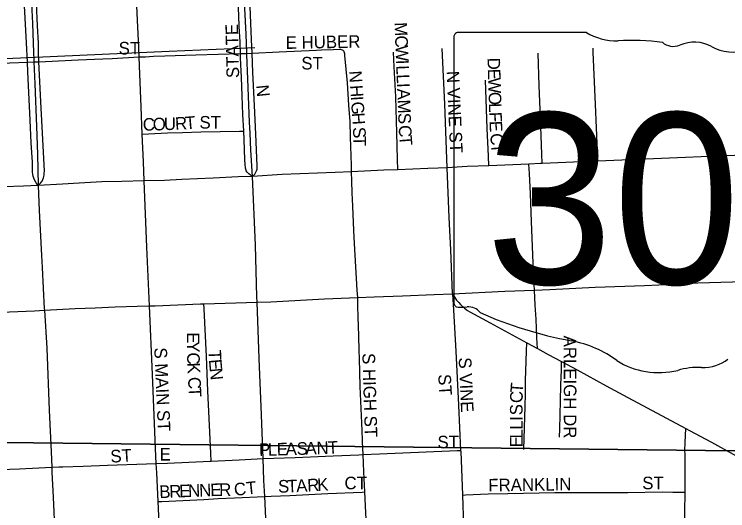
# Model space of a CAD drawing. Extents: x -97 to 34, y -21 to 22.
# Drawn here: x 5.626 to 6.163, y 19.422 to 19.796 of the extents above; entities that cross this region are included whole.
import ezdxf

# ---------------------------------------------------------------- set-up
doc = ezdxf.new("R2010")
doc.units = 0
for name, color, linetype in [('GM_X_City_Street', 7, 'Continuous'), ('GM_X_City_Street_Text', 7, 'Continuous'), ('GM_X_Rail_Line', 7, 'Continuous'), ('GM_X_Section', 7, 'Continuous'), ('GM_X_State_Location', 7, 'Continuous'), ('GM_X_State_Route', 7, 'Continuous'), ('GM_X_State_Shield', 7, 'Continuous')]:
    doc.layers.add(name, color=color, linetype=linetype)

msp = doc.modelspace()

# ---------------------------------------------------------------- linework, layer by layer
at = {"layer": 'GM_X_City_Street'}
for points in [[(5.71984, 19.76387), (5.71944, 19.77089), (5.71848, 19.79156), (5.71627, 19.84134), (5.71468, 19.87863), (5.7134, 19.90538)], [(5.64434, 19.76026), (5.64409, 19.76775), (5.64386, 19.77424), (5.64327, 19.7874), (5.64248, 19.8043), (5.64189, 19.82119), (5.64071, 19.84279), (5.63971, 19.87305), (5.63831, 19.90448)], [(5.63571, 19.75992), (5.63503, 19.77443), (5.63345, 19.80233), (5.63226, 19.82629), (5.63127, 19.85006), (5.63029, 19.87677), (5.63016, 19.87977)], [(5.79599, 19.76644), (5.7957, 19.77526), (5.79511, 19.78685), (5.79491, 19.7951), (5.79333, 19.82692), (5.79319, 19.82924)], [(5.80474, 19.76668), (5.80433, 19.77702), (5.80296, 19.8082), (5.80228, 19.82381), (5.80206, 19.82962)], [(5.71984, 19.76387), (5.72445, 19.76407), (5.73055, 19.76433), (5.73918, 19.7647), (5.76245, 19.7655), (5.79599, 19.76644)], [(5.79599, 19.76644), (5.80006, 19.76655), (5.80077, 19.76657), (5.80474, 19.76668)], [(5.79845, 19.70802), (5.79788, 19.72046), (5.79729, 19.7346), (5.79689, 19.74835), (5.7961, 19.76289), (5.79599, 19.76644)], [(5.80474, 19.76668), (5.8251, 19.76778), (5.8533, 19.76903), (5.85707, 19.76923), (5.86585, 19.76954), (5.87049, 19.76971), (5.87123, 19.76962), (5.87195, 19.76949), (5.87257, 19.76925), (5.87301, 19.76903), (5.87363, 19.76853)], [(5.80513, 19.67386), (5.80685, 19.67552), (5.80771, 19.67697), (5.80818, 19.67797), (5.80856, 19.67946), (5.80861, 19.68035), (5.80866, 19.68173), (5.80749, 19.70559), (5.80663, 19.72735), (5.8054, 19.75224), (5.80474, 19.76668)], [(5.87971, 19.67732), (5.87956, 19.68234), (5.87893, 19.70348), (5.8785, 19.71536), (5.87765, 19.72753), (5.87648, 19.74446), (5.87466, 19.76485), (5.87457, 19.76616), (5.87441, 19.76685), (5.87416, 19.76759), (5.87397, 19.76809), (5.87363, 19.76853)], [(5.91454, 19.67892), (5.91433, 19.68698), (5.91383, 19.70674), (5.91296, 19.73388), (5.91177, 19.7564), (5.91118, 19.76754)], [(5.95158, 19.6803), (5.94981, 19.72821), (5.94777, 19.7701)], [(6.02321, 19.68359), (6.02294, 19.69067), (6.0219, 19.71818), (6.021, 19.7422), (6.02007, 19.76675)], [(6.06508, 19.68531), (6.06477, 19.69278), (6.06326, 19.72813), (6.0616, 19.76752), (6.06143, 19.77055)], [(5.56126, 19.75673), (5.56745, 19.75698), (5.60894, 19.75891), (5.63571, 19.75992)], [(5.63571, 19.75992), (5.64055, 19.76011), (5.64155, 19.76015), (5.64434, 19.76026)], [(5.64379, 19.66695), (5.64221, 19.6691), (5.64078, 19.67186), (5.64004, 19.67399), (5.63974, 19.67542), (5.63954, 19.67726), (5.63937, 19.68467), (5.63838, 19.6992), (5.63759, 19.71629), (5.63602, 19.75263), (5.63571, 19.75992)], [(5.64379, 19.66695), (5.64536, 19.66876), (5.64668, 19.67038), (5.64765, 19.67293), (5.64812, 19.67475), (5.64829, 19.6763), (5.64846, 19.67775), (5.64675, 19.71132), (5.64564, 19.72999), (5.64466, 19.75027), (5.64434, 19.76026)], [(5.64434, 19.76026), (5.64913, 19.76043), (5.67383, 19.76162), (5.69238, 19.76252), (5.69953, 19.76275), (5.71984, 19.76387)], [(5.72212, 19.70578), (5.72135, 19.72628), (5.72007, 19.75727), (5.71984, 19.76387)], [(5.98298, 19.68197), (5.98265, 19.68914), (5.9817, 19.71003), (5.98051, 19.74646)], [(5.72212, 19.70578), (5.74113, 19.70662), (5.75248, 19.707), (5.7662, 19.70747), (5.79521, 19.70797), (5.79845, 19.70802)], [(5.80513, 19.67386), (5.80355, 19.67478), (5.80238, 19.67575), (5.80116, 19.67697), (5.80036, 19.67815), (5.80027, 19.67851), (5.79984, 19.68014), (5.79958, 19.68311), (5.7994, 19.68624), (5.79873, 19.70176), (5.79845, 19.70802)], [(5.72347, 19.67047), (5.7231, 19.68486), (5.72212, 19.70578)], [(6.01729, 19.5883), (6.01713, 19.59209), (6.017, 19.59522), (6.01644, 19.60855), (6.01511, 19.64001), (6.01424, 19.66069), (6.0135, 19.67603), (6.01316, 19.68319)], [(5.8843, 19.5826), (5.8839, 19.58809), (5.88193, 19.62328), (5.88139, 19.63315), (5.88056, 19.65153), (5.88011, 19.66147), (5.87988, 19.67028), (5.87971, 19.67732)], [(5.72755, 19.5763), (5.7256, 19.6205), (5.72347, 19.67047)], [(6.01958, 19.54419), (6.01921, 19.55233), (6.01856, 19.56626), (6.01795, 19.57692), (6.01729, 19.5883)], [(5.95576, 19.58544), (5.9565, 19.57314), (5.95805, 19.54225), (5.96017, 19.50147), (5.96177, 19.46753)], [(5.77401, 19.45943), (5.77365, 19.46553), (5.7732, 19.47589), (5.77157, 19.51235), (5.77042, 19.53827), (5.76866, 19.57404), (5.76846, 19.57799)], [(5.88827, 19.46441), (5.88788, 19.47391), (5.88779, 19.47532), (5.8877, 19.48214), (5.88732, 19.48798), (5.88613, 19.51563), (5.88551, 19.53685), (5.88536, 19.54242), (5.88506, 19.55382), (5.88468, 19.56807), (5.88447, 19.57621), (5.8843, 19.5826)], [(5.73268, 19.45753), (5.73243, 19.46283), (5.72982, 19.52467), (5.72755, 19.5763)], [(6.00938, 19.46825), (6.00983, 19.48455), (6.01027, 19.50071), (6.01047, 19.50976), (6.0107, 19.52014), (6.01113, 19.53477), (6.01144, 19.54245), (6.01168, 19.54848)], [(6.03623, 19.47755), (6.03644, 19.48387), (6.037, 19.50478), (6.03731, 19.51652), (6.03763, 19.52829), (6.03779, 19.5344)], [(6.13076, 19.43609), (6.13082, 19.44287), (6.13071, 19.46451), (6.13066, 19.4674), (6.13086, 19.47346), (6.13122, 19.48405)], [(5.88827, 19.46441), (5.9008, 19.46495), (5.95337, 19.46723), (5.95927, 19.46745), (5.96177, 19.46753)], [(5.96177, 19.46753), (5.96181, 19.46666), (5.96306, 19.43384)], [(5.73268, 19.45753), (5.74119, 19.45792), (5.77318, 19.45939), (5.77401, 19.45943)], [(5.77401, 19.45943), (5.79504, 19.46039), (5.81305, 19.46133)], [(5.81305, 19.46133), (5.83708, 19.46224), (5.86569, 19.46339), (5.8851, 19.46424), (5.88827, 19.46441)], [(5.88954, 19.4362), (5.88882, 19.45136), (5.88827, 19.46441)], [(5.5894, 19.45308), (5.59252, 19.45286), (5.59702, 19.45276), (5.60216, 19.45276), (5.60759, 19.45287), (5.62955, 19.45365), (5.65397, 19.45497)], [(5.65397, 19.45497), (5.65933, 19.45505), (5.66239, 19.45509), (5.67764, 19.45571), (5.69594, 19.45635), (5.72521, 19.45749), (5.73268, 19.45753)], [(5.73394, 19.42898), (5.73299, 19.45068), (5.73268, 19.45753)], [(5.73394, 19.42898), (5.73673, 19.42911), (5.76855, 19.43056), (5.77932, 19.43126), (5.79159, 19.43167), (5.81426, 19.43276)], [(5.81426, 19.43276), (5.81913, 19.43304), (5.83324, 19.43358), (5.86175, 19.43493), (5.88776, 19.43612), (5.88954, 19.4362)], [(5.89109, 19.40348), (5.89103, 19.40499), (5.88954, 19.4362)], [(5.96306, 19.43384), (5.9655, 19.43395), (5.98248, 19.43476), (5.99727, 19.43516), (6.03263, 19.43577), (6.05351, 19.43567), (6.07109, 19.43577), (6.08753, 19.43589), (6.11356, 19.43618), (6.12149, 19.4361), (6.12864, 19.43609), (6.13076, 19.43609)], [(5.96306, 19.43384), (5.96394, 19.41059), (5.96445, 19.39593), (5.96525, 19.37289)], [(6.1299, 19.37581), (6.13076, 19.43609)], [(5.7355, 19.39632), (5.73394, 19.42898)]]:
    msp.add_lwpolyline(points, dxfattribs=at)
at = {"layer": 'GM_X_Rail_Line'}
for points in [[(5.12506, 19.74133), (5.25397, 19.74658), (5.45064, 19.75541), (5.56834, 19.76047), (5.74228, 19.76816), (5.80143, 19.7707)], [(5.80143, 19.7707), (5.80685, 19.77094)]]:
    msp.add_lwpolyline(points, dxfattribs=at)
at = {"layer": 'GM_X_Section'}
for points in [[(5.59805, 20.47457), (6.61045, 20.46615), (6.60805, 19.46219), (5.59615, 19.47364)], [(5.59615, 19.47364), (6.60805, 19.46219), (6.59547, 18.46625), (5.59082, 18.47236)]]:
    msp.add_lwpolyline(points, close=True, dxfattribs=at)
at = {"layer": 'GM_X_State_Route'}
for points in [[(5.80294, 19.71473), (5.8016, 19.74704), (5.8008, 19.76569), (5.80077, 19.76657), (5.80019, 19.78098), (5.79942, 19.80041), (5.79882, 19.81541), (5.79809, 19.82947), (5.79783, 19.83465), (5.79637, 19.86532), (5.79443, 19.90607)], [(5.63488, 19.88036), (5.63635, 19.85068), (5.63754, 19.82581), (5.63863, 19.80411), (5.63934, 19.78901), (5.64023, 19.76731), (5.64048, 19.76193), (5.64055, 19.76011), (5.64121, 19.74363), (5.64237, 19.71146), (5.64311, 19.69074), (5.64379, 19.66695)], [(5.80513, 19.67386), (5.8039, 19.69366), (5.80328, 19.70639), (5.80294, 19.71473)], [(6.2824, 19.69496), (6.27871, 19.69569), (6.27535, 19.69613), (6.2727, 19.69636), (6.26992, 19.69643), (6.26402, 19.69609), (6.26088, 19.69554), (6.25635, 19.69475), (6.25295, 19.69377), (6.25069, 19.69347), (6.24738, 19.69338), (6.24339, 19.69315), (6.21975, 19.6918), (6.19129, 19.69058), (6.17504, 19.68989), (6.16102, 19.68929), (6.06508, 19.68531), (6.0528, 19.6848), (6.02321, 19.68359), (6.022, 19.68354), (6.01316, 19.68319)], [(5.95158, 19.6803), (5.94476, 19.68005), (5.93708, 19.67979), (5.91454, 19.67892), (5.90386, 19.67851), (5.87971, 19.67732), (5.86728, 19.6767), (5.82752, 19.6752), (5.80513, 19.67386)], [(6.01316, 19.68319), (5.98298, 19.68197), (5.96675, 19.68133), (5.95158, 19.6803)], [(5.95576, 19.58544), (5.9545, 19.61853), (5.95325, 19.64283), (5.95158, 19.6803)], [(5.80513, 19.67386), (5.7942, 19.67345), (5.77557, 19.67252), (5.75177, 19.67144), (5.73886, 19.67086), (5.72347, 19.67047), (5.70681, 19.67006), (5.69163, 19.66967), (5.67471, 19.66884), (5.66198, 19.66793), (5.64379, 19.66695)], [(5.80859, 19.57918), (5.80843, 19.58323), (5.80722, 19.62219), (5.80513, 19.67386)], [(5.64379, 19.66695), (5.63272, 19.66657), (5.61797, 19.66597)], [(5.64379, 19.66695), (5.64439, 19.64813), (5.64623, 19.61441), (5.64678, 19.60515), (5.64836, 19.5741), (5.64841, 19.57304)], [(5.95576, 19.58544), (5.99491, 19.58745), (6.01729, 19.5883), (6.02898, 19.58874), (6.06304, 19.59041), (6.10023, 19.59161), (6.12188, 19.59268), (6.14044, 19.59362), (6.18384, 19.59508), (6.19092, 19.59539), (6.23649, 19.5976), (6.25248, 19.59818), (6.26864, 19.59883)], [(5.80859, 19.57918), (5.81893, 19.57949), (5.8594, 19.58157), (5.8843, 19.5826), (5.89674, 19.58312), (5.9181, 19.58393), (5.94179, 19.58493), (5.95576, 19.58544)], [(5.95576, 19.58544), (5.95876, 19.58069), (5.9603, 19.57889), (5.96164, 19.57748), (5.96459, 19.57473), (5.96698, 19.57292), (5.9687, 19.57194), (5.9839, 19.56359), (6.01168, 19.54848), (6.01958, 19.54419), (6.02762, 19.53981), (6.03779, 19.5344), (6.0496, 19.52813), (6.07143, 19.51623), (6.08773, 19.50736), (6.13122, 19.48405), (6.13415, 19.48248), (6.15056, 19.47363), (6.18319, 19.45558)], [(5.64841, 19.57304), (5.67162, 19.5744), (5.68676, 19.57493), (5.70181, 19.57555), (5.71825, 19.57602), (5.72755, 19.5763), (5.73176, 19.57648), (5.766, 19.57792), (5.76846, 19.57799), (5.80859, 19.57918)], [(5.81579, 19.40021), (5.81426, 19.43276), (5.81368, 19.44493), (5.81305, 19.46133), (5.81178, 19.49422), (5.81007, 19.53664), (5.80859, 19.57918)], [(5.33723, 19.56139), (5.33859, 19.56129), (5.35022, 19.56126), (5.35928, 19.5612), (5.36561, 19.5614), (5.37168, 19.5616), (5.39822, 19.56258), (5.39939, 19.56263), (5.43943, 19.56406), (5.46119, 19.56492), (5.47611, 19.56559), (5.49206, 19.56631), (5.55649, 19.56914), (5.56633, 19.56957), (5.58408, 19.57029), (5.64107, 19.5726), (5.64841, 19.57304)], [(5.64841, 19.57304), (5.65021, 19.54453), (5.65196, 19.49769), (5.65352, 19.46651), (5.65397, 19.45497), (5.65413, 19.45102), (5.65492, 19.4323), (5.65622, 19.40416), (5.65663, 19.39506)]]:
    msp.add_lwpolyline(points, dxfattribs=at)
at = {"layer": 'GM_X_State_Shield'}
for p, q in [((6.05653, 19.78232), (5.96001, 19.78232)), ((5.95676, 19.77887), (5.95676, 19.57875))]:
    msp.add_line(p, q, dxfattribs=at)
for centre, major_axis, start_param, end_param in [((5.96054, 19.7793), (0.00382, 0), 1.712693, 3.28349), ((6.07951, 19.80555), (0.03703, 0), 4.042523, 4.731795), ((6.09179, 19.66997), (0.13295, 0), 1.404758, 1.657858), ((6.13766, 19.75721), (0.02221, 0), 0.950623, 2.079405), ((6.12198, 19.78034), (0.01068, 0), 3.836095, 5.185415), ((6.16633, 19.78893), (0.02672, 0), 4.081561, 5.145723), ((5.96057, 19.57831), (0.00385, 0), 3.00124, 4.508301), ((5.96116, 19.59879), (0.0294, 0), 4.665946, 4.897461), ((5.96717, 19.56721), (0.0106, 0), 0.519207, 1.627899), ((6.101, 19.74701), (0.2524, 0), 4.195997, 4.488961), ((6.02575, 19.48885), (0.07897, 0), 0.823519, 1.323587), ((6.11116, 19.56621), (0.05011, 0), 4.026481, 4.996735), ((6.14377, 19.55123), (0.0267, 0), 4.691044, 5.507374), ((6.14011, 19.49702), (0.04118, 0), 1.495662, 1.94098)]:
    msp.add_ellipse(centre, major_axis=major_axis, ratio=0.8, start_param=start_param, end_param=end_param, dxfattribs=at)

# ---------------------------------------------------------------- texts
at = {"layer": 'GM_X_City_Street_Text'}
for s, rotation, p in [('STATE', 91.3016, (5.79505, 19.74804)), ('M', 272.2957, (5.91194, 19.78985)), ('E HUBER', 0.9856, (5.83012, 19.76989)), ('C', 272.2975, (5.91234, 19.77986)), ('ST', 0, (5.70433, 19.76573)), ('W', 272.2873, (5.91264, 19.77237)), ('ST', 0, (5.84183, 19.75443)), ('I', 272.3089, (5.91307, 19.76154)), ('D', 271.7926, (5.98194, 19.76317)), ('L', 272.2961, (5.91324, 19.75737)), ('N', 273.7836, (5.87777, 19.75323)), ('L', 272.2903, (5.91351, 19.75071)), ('N VINE ST', 272.6024, (5.95111, 19.75314)), ('E', 271.8022, (5.9822, 19.75483)), ('W', 271.8088, (5.98241, 19.74817)), ('N', 275.7063, (5.80776, 19.74246)), ('H', 273.7836, (5.87849, 19.74241)), ('I', 272.2912, (5.91378, 19.74405)), ('A', 272.2923, (5.91395, 19.73989)), ('I', 273.8185, (5.87904, 19.73409)), ('O', 271.7926, (5.98275, 19.73734)), ('G', 273.7836, (5.87932, 19.72993)), ('M', 272.2937, (5.91428, 19.73157)), ('L', 271.7891, (5.98301, 19.72901)), ('C', 1.6276, (5.72261, 19.70823)), ('O', 1.6178, (5.73011, 19.70844)), ('U', 1.6154, (5.73844, 19.70868)), ('R', 2.7844, (5.74697, 19.70892)), ('T', 4.8442, (5.75483, 19.70931)), ('ST', 0, (5.76516, 19.7099)), ('H', 273.8171, (5.87987, 19.72161)), ('S', 272.2903, (5.91468, 19.72158)), ('F', 271.7891, (5.98322, 19.72235)), ('C', 273.0577, (5.91505, 19.71227)), ('E', 272.6285, (5.98344, 19.71554)), ('S', 273.3617, (5.88058, 19.71082)), ('T', 270.9562, (5.88097, 19.70427)), ('T', 274.4938, (5.91547, 19.70453)), ('C', 274.6379, (5.98394, 19.70602)), ('T', 274.7691, (5.98455, 19.69852)), ('E', 270.0547, (5.75565, 19.55644)), ('ARLEIGH DR', 270, (6.03944, 19.55394)), ('Y', 270.7362, (5.75566, 19.54965)), ('S MAIN ST', 272.5248, (5.73111, 19.54485)), ('C', 271.5494, (5.75577, 19.54117)), ('T', 272.0766, (5.77194, 19.54302)), ('S HIGH ST', 271.7079, (5.88777, 19.54067)), ('E', 274.9931, (5.77221, 19.53584)), ('S VINE', 272.6012, (5.96027, 19.53736)), ('K', 272.4961, (5.75598, 19.53351)), ('N', 275.4423, (5.7728, 19.52912)), ('ST', 273.5746, (5.94484, 19.52471)), ('C', 273.0455, (5.75647, 19.52259)), ('T', 85.7061, (6.00854, 19.51043)), ('T', 273.1168, (5.75687, 19.51508)), ('C', 88.8829, (6.0084, 19.50307)), ('S', 89.9707, (6.00839, 19.49395)), ('I', 89.9563, (6.00839, 19.48978)), ('L', 89.9707, (6.00839, 19.48311)), ('L', 89.9453, (6.00838, 19.47644)), ('ST', 0, (5.94433, 19.46906)), ('E', 89.9727, (6.00838, 19.46978)), ('P', 1.7216, (5.81011, 19.46322)), ('L', 1.7216, (5.81677, 19.46342)), ('E', 1.7216, (5.82343, 19.46362)), ('A', 1.7052, (5.8301, 19.46383)), ('S', 1.714, (5.83843, 19.46407)), ('A', 1.7172, (5.84509, 19.46427)), ('N', 1.7052, (5.85342, 19.46452)), ('T', 2.7915, (5.86195, 19.46478)), ('ST', 3.5738, (5.69838, 19.45822)), ('E', 0, (5.73516, 19.45989)), ('CT', 6.0054, (5.79164, 19.43322)), ('S', 0.2732, (5.82434, 19.43573)), ('T', 1.9272, (5.8313, 19.43577)), ('A', 3.1505, (5.83819, 19.436)), ('R', 3.1764, (5.84651, 19.43645)), ('K', 3.1713, (5.854, 19.43687)), ('CT', 0, (5.87433, 19.43823)), ('FRANKLIN', 0.8201, (5.98262, 19.43656)), ('ST', 0, (6.09849, 19.43823)), ('B', 2.1373, (5.73509, 19.43156)), ('R', 2.155, (5.74259, 19.43184)), ('E', 2.1312, (5.75008, 19.43212)), ('N', 2.1453, (5.75675, 19.43237)), ('N', 2.1421, (5.76508, 19.43268)), ('E', 1.6397, (5.77338, 19.43299)), ('R', 0.34, (5.77999, 19.43318))]:
    msp.add_text(s, height=0.00947, rotation=rotation, dxfattribs=at).set_placement(p)
at = {"layer": 'GM_X_State_Location'}
for s in ['s', 'r']:
    msp.add_text(s, height=0.000189, dxfattribs=at).set_placement((6.11785, 19.66551))
msp.add_text('309D', height=0.000189, rotation=0, dxfattribs=at).set_placement((6.03766, 19.65719))
at = {"layer": 'GM_X_State_Shield'}
msp.add_text('309D', height=0.128788, dxfattribs=at).set_placement((5.98063, 19.59286))

doc.saveas('drawing.dxf')
